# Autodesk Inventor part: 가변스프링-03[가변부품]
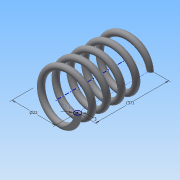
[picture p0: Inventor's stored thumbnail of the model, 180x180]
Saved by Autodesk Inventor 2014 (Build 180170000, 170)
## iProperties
Created: 2015-09
Part Number: 가변스프링-03[가변부품]
Material: 강철, 탄소
Document SubType Name: Modeling
Designer: study
Density: 7.87 g/cm^3
Appearance: 반연마
Mass: 18.9154 g
Surface Area: 32.5802 cm^2
Volume: 2.40348 cm^3
Author: study
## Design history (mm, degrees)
sketch "스케치1"
  geometry: L1 (0, 0)-(11, 0); L2 (11, 0)-(11, 36.411); L3 (11, 36.411)-(0, 36.411); L4 (0, 36.411)-(0, 0); C1 r 1.5 at (11, 0)
  constraints: 8 end point, 2 parallel, 1 centre point, 1 coincident, 1 horizontal, 1 perpendicular
  dimensions: "d0" = 22 diameter of L2 L4; "d1" = 36.4112 distance of L1.end L2.end (derived); "d2" = 3 diameter of C1
feature "코일1" sketch "스케치1" pitch "d3" = 10; turns "d5" = 5; dims "d4" = 36.4112 (= d1), "d6" = 0, angle "d7" = 90 deg, angle "d8" = 90 deg, "d9" = 0, "d10" = 0
sketch "스케치2"
  geometry: L1 (-12.5, 0)-(-9.5, 0) reference; L2 (-12.5, 0)-(-9.5, 0) reference; 1 further point
  constraints: 2 horizontal alignment
extrude "돌출1" cut sketch "스케치2" stored distance "d11" = 10; taper "d12" = 0 deg
node "작업 평면1"
sketch "스케치3"
  geometry: L1 (-9.5, 0)-(-12.5, 0) reference; 1 further point
  constraints: 1 horizontal alignment
extrude "돌출2" cut sketch "스케치3" stored distance "d14" = 10; taper "d15" = 0 deg
node "솔리드1"
node "절단 모서리 투영1"
node "절단 모서리 투영2"
node "절단 모서리 투영3"
other parameters: "d13" = 36.4112 (= d1)
